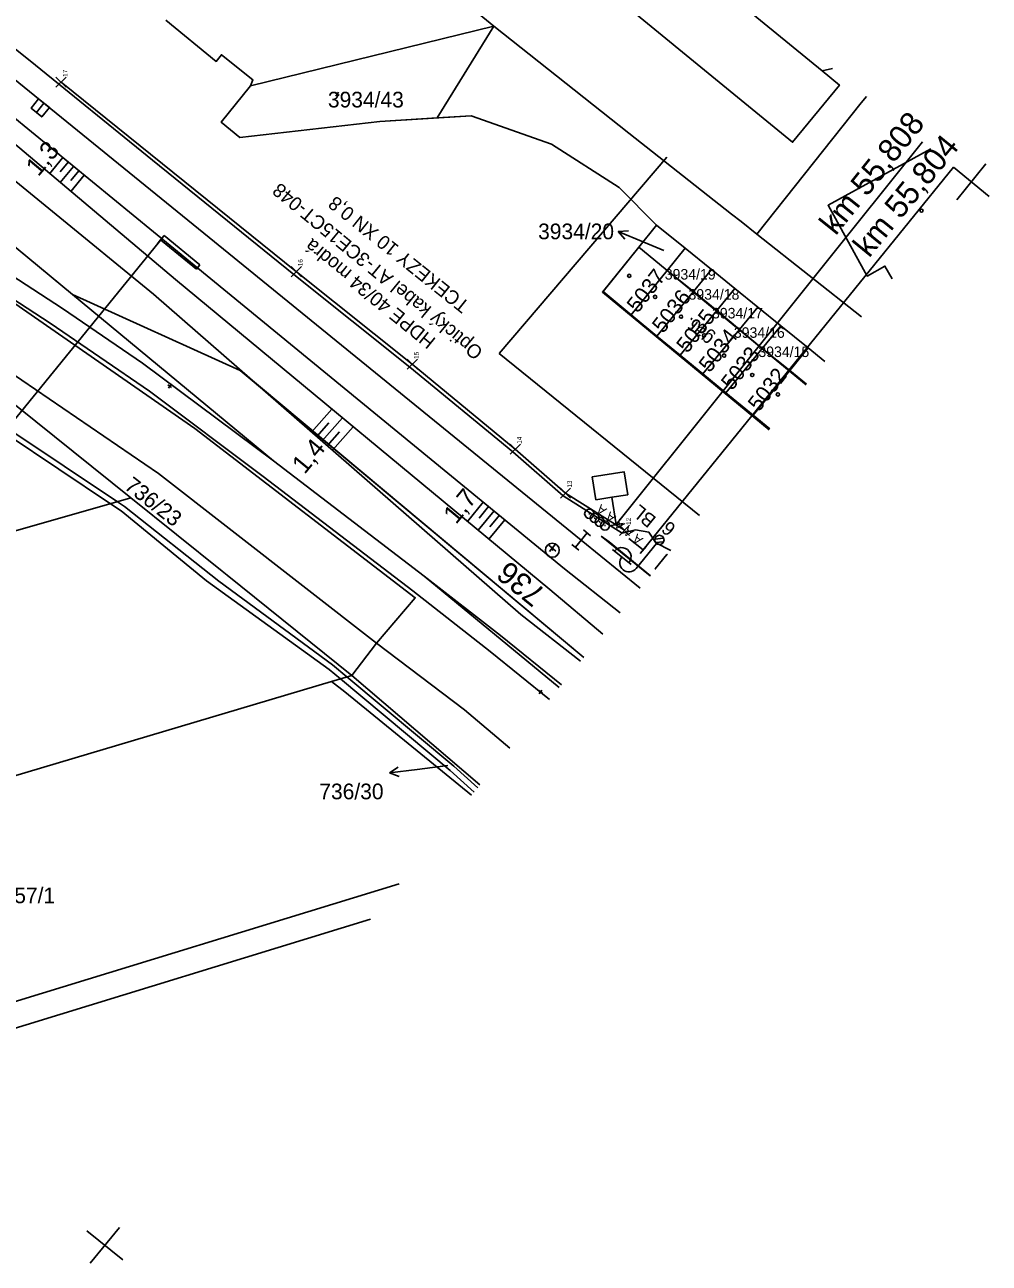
# Model space of a CAD drawing. Extents: x -834676 to -834416, y -1108532 to -1108280.
# Drawn here: x -834520.4 to -834416, y -1108532 to -1108397.9 of the extents above; entities that cross this region are included whole.
import ezdxf

# ---------------------------------------------------------------- set-up
doc = ezdxf.new("R2010")
doc.units = 0
for name, color, linetype in [('Hranice parcel', 7, 'Continuous'), ('Parcelní čísla', 7, 'Continuous'), ('Pop  PČ popisy', 7, 'Continuous'), ('PS 1301 GDIS Nový stav_Prvky_1000', 7, 'Continuous'), ('PS 1301 GDIS Nový stav_Trasa', 7, 'Continuous'), ('PS 1301 LomBod_popis', 7, 'Continuous'), ('PS 1301 LomBod_prvek', 7, 'Continuous'), ('Vnitřní kresba', 7, 'Continuous'), ('Vrstva 1', 7, 'Continuous'), ('Vrstva 14', 7, 'Continuous'), ('Vrstva 17', 7, 'Continuous'), ('Vrstva 23', 7, 'Continuous'), ('Vrstva 25', 7, 'Continuous'), ('Vrstva 27', 7, 'Continuous'), ('Vrstva 3', 7, 'Continuous'), ('Vrstva 32', 7, 'Continuous'), ('Vrstva 33', 7, 'Continuous'), ('Vrstva 48', 7, 'Continuous'), ('Vrstva 49', 7, 'Continuous'), ('Vrstva 53', 7, 'Continuous'), ('Vrstva 6', 7, 'Continuous'), ('Vrstva 60', 7, 'Continuous'), ('Vrstva 63', 7, 'Continuous'), ('Vrstva 7', 7, 'Continuous'), ('Vrstva 9', 7, 'Continuous'), ('Věcná břemena k části', 7, 'Continuous'), ('Značky budov', 7, 'Continuous')]:
    doc.layers.add(name, color=color, linetype=linetype)

msp = doc.modelspace()

# ---------------------------------------------------------------- linework, layer by layer
at = {"layer": 'Hranice parcel'}
for p, q in [((-834495.96, -1108404.56), (-834469.64, -1108398.1)), ((-834469.64, -1108398.1), (-834475.78, -1108408.03)), ((-834495.96, -1108404.56), (-834495.7, -1108403.89)), ((-834542.17, -1108404.85), (-834515.24, -1108427.13)), ((-834441.15, -1108420.61), (-834429.87, -1108406.4)), ((-834453.93, -1108422.01), (-834452.01, -1108419.63)), ((-834452.01, -1108419.63), (-834448.91, -1108422.14)), ((-834441.15, -1108420.61), (-834442.87, -1108419.25)), ((-834542.58, -1108422.11), (-834508.91, -1108449.17)), ((-834450.86, -1108424.54), (-834453.93, -1108422.01)), ((-834448.91, -1108422.14), (-834450.86, -1108424.54)), ((-834448.91, -1108422.14), (-834446.07, -1108424.44)), ((-834450.86, -1108424.54), (-834454.78, -1108429.35)), ((-834448.01, -1108426.81), (-834450.86, -1108424.54)), ((-834446.07, -1108424.44), (-834448.01, -1108426.81)), ((-834446.07, -1108424.44), (-834443.54, -1108426.49)), ((-834448.01, -1108426.81), (-834451.98, -1108431.65)), ((-834445.51, -1108428.88), (-834448.01, -1108426.81)), ((-834443.54, -1108426.49), (-834445.51, -1108428.88)), ((-834443.54, -1108426.49), (-834441.06, -1108428.5)), ((-834515.24, -1108427.13), (-834493.48, -1108445.13)), ((-834451.98, -1108431.65), (-834454.78, -1108429.35)), ((-834445.51, -1108428.88), (-834449.47, -1108433.71)), ((-834443.05, -1108430.92), (-834445.51, -1108428.88)), ((-834441.06, -1108428.5), (-834443.05, -1108430.92)), ((-834441.06, -1108428.5), (-834438.56, -1108430.52)), ((-834443.05, -1108430.92), (-834447, -1108435.74)), ((-834440.59, -1108433), (-834443.05, -1108430.92)), ((-834438.56, -1108430.52), (-834440.59, -1108433)), ((-834438.56, -1108430.52), (-834435.6, -1108432.92)), ((-834449.47, -1108433.71), (-834451.98, -1108431.65)), ((-834447, -1108435.74), (-834449.47, -1108433.71)), ((-834440.59, -1108433), (-834444.51, -1108437.78)), ((-834437.6, -1108435.37), (-834440.59, -1108433)), ((-834435.6, -1108432.92), (-834437.6, -1108435.37)), ((-834435.6, -1108432.92), (-834433.79, -1108434.39)), ((-834444.51, -1108437.78), (-834447, -1108435.74)), ((-834437.6, -1108435.37), (-834441.56, -1108440.19)), ((-834435.8, -1108436.85), (-834437.6, -1108435.37)), ((-834441.56, -1108440.19), (-834444.51, -1108437.78)), ((-834439.74, -1108441.69), (-834441.56, -1108440.19)), ((-834493.48, -1108445.13), (-834477.16, -1108457.63)), ((-834508.91, -1108449.17), (-834551.74, -1108461.32)), ((-834485, -1108468.39), (-834482.32, -1108464.89)), ((-834487.2, -1108469.05), (-834485, -1108468.39)), ((-834471.13, -1108480.23), (-834485, -1108468.39)), ((-834560.03, -1108490.74), (-834487.2, -1108469.05)), ((-834537.95, -1108508.73), (-834479.86, -1108490.95)), ((-834535.36, -1108510.83), (-834482.97, -1108494.76))]:
    msp.add_line(p, q, dxfattribs=at)
for points in [[(-834434.08, -1108402.94), (-834432.22, -1108404.46), (-834437.29, -1108410.65), (-834462.92, -1108389.64), (-834463.74, -1108390.64), (-834501.14, -1108359.98), (-834500.32, -1108358.97), (-834494.92, -1108352.25)], [(-834469.64, -1108398.1), (-834485.11, -1108385.4), (-834501.55, -1108372.58)], [(-834495.7, -1108403.89), (-834499.11, -1108401.19), (-834499.68, -1108401.9), (-834505.13, -1108397.43)], [(-834442.87, -1108419.25), (-834443.89, -1108418.44), (-834455.01, -1108409.66), (-834469.64, -1108398.1)], [(-834432.99, -1108402.69), (-834434.08, -1108402.94)], [(-834475.78, -1108408.03), (-834481.96, -1108408.42), (-834497.12, -1108410.14), (-834499.16, -1108408.48), (-834495.96, -1108404.56)], [(-834429.87, -1108406.4), (-834429.31, -1108405.69)], [(-834452.01, -1108419.63), (-834456.08, -1108415.54), (-834463.39, -1108410.86), (-834472.09, -1108407.8), (-834475.78, -1108408.03)], [(-834482.32, -1108464.89), (-834478.13, -1108459.97), (-834501.98, -1108441.64), (-834521.49, -1108428.13), (-834543.43, -1108413.95), (-834549.21, -1108409.83)], [(-834493.48, -1108445.13), (-834507.66, -1108434.56), (-834516.33, -1108428.66), (-834541.81, -1108412.04), (-834542.9, -1108413.77)], [(-834422.34, -1108411.36), (-834433.45, -1108417.48), (-834429.22, -1108425.14), (-834427.3, -1108424.07), (-834426.51, -1108425.45)], [(-834463.6, -1108470.98), (-834470.02, -1108465.8), (-834478.4, -1108459.23), (-834494.59, -1108446.84), (-834506.89, -1108437.61), (-834517.65, -1108430.23), (-834542.9, -1108413.77)], [(-834429.85, -1108429.55), (-834441.15, -1108420.61)], [(-834542.58, -1108422.11), (-834525.2, -1108433.38), (-834505.92, -1108446.53), (-834482.32, -1108464.89)], [(-834454.78, -1108429.35), (-834457.81, -1108426.82), (-834453.93, -1108422.01)], [(-834459.9, -1108466.45), (-834497.07, -1108435.35), (-834515.24, -1108427.13)], [(-834508.91, -1108449.17), (-834499.04, -1108457.11), (-834498.51, -1108457.53), (-834485, -1108468.39)], [(-834477.16, -1108457.63), (-834468.9, -1108464.07), (-834462.3, -1108469.39)], [(-834462.56, -1108469.7), (-834477.16, -1108457.63)], [(-834482.32, -1108464.89), (-834472.79, -1108472.12), (-834467.9, -1108476.27)], [(-834472.04, -1108481.34), (-834485.74, -1108470.15), (-834487.2, -1108469.05)]]:
    msp.add_lwpolyline(points, dxfattribs=at)
at = {"layer": 'Pop  PČ popisy'}
for p, q in [((-834456.16, -1108420.31), (-834455.05, -1108420.24)), ((-834453.4, -1108421.48), (-834456.16, -1108420.31)), ((-834456.16, -1108420.31), (-834455.44, -1108421.16)), ((-834451.23, -1108422.39), (-834453.4, -1108421.48)), ((-834480.92, -1108478.94), (-834479.99, -1108478.32)), ((-834477.94, -1108478.57), (-834480.92, -1108478.94)), ((-834480.92, -1108478.94), (-834479.86, -1108479.31)), ((-834474.6, -1108478.13), (-834477.94, -1108478.57))]:
    msp.add_line(p, q, dxfattribs=at)
at = {"layer": 'PS 1301 GDIS Nový stav_Prvky_1000'}
for points in [[(-834518.9, -1108405.95), (-834517.74, -1108406.9), (-834518.56, -1108407.91), (-834519.72, -1108406.96)], [(-834517.74, -1108406.9), (-834518.32, -1108406.43), (-834519.14, -1108407.44), (-834518.56, -1108407.91)]]:
    msp.add_lwpolyline(points, close=True, dxfattribs=at)
at = {"layer": 'PS 1301 GDIS Nový stav_Trasa'}
msp.add_lwpolyline([(-834455.48, -1108452.67), (-834461.87, -1108448.64), (-834467.31, -1108443.89), (-834478.46, -1108434.69), (-834491, -1108424.67), (-834516.47, -1108404.15)], dxfattribs=at)
at = {"layer": 'PS 1301 LomBod_prvek'}
for p, q in [((-834517.02, -1108404.7), (-834515.92, -1108403.6)), ((-834515.92, -1108404.7), (-834517.02, -1108403.6)), ((-834516.47, -1108404.15), (-834516.47, -1108404.15)), ((-834491.55, -1108425.22), (-834490.45, -1108424.12)), ((-834490.45, -1108425.22), (-834491.55, -1108424.12)), ((-834491, -1108424.67), (-834491, -1108424.67)), ((-834479.01, -1108435.24), (-834477.91, -1108434.14)), ((-834477.91, -1108435.24), (-834479.01, -1108434.14)), ((-834478.46, -1108434.69), (-834478.46, -1108434.69)), ((-834467.86, -1108444.44), (-834466.76, -1108443.34)), ((-834466.76, -1108444.44), (-834467.86, -1108443.34)), ((-834467.31, -1108443.89), (-834467.31, -1108443.89)), ((-834462.42, -1108449.19), (-834461.32, -1108448.09)), ((-834461.32, -1108449.19), (-834462.42, -1108448.09)), ((-834461.87, -1108448.64), (-834461.87, -1108448.64)), ((-834456.03, -1108453.22), (-834454.93, -1108452.12)), ((-834454.93, -1108453.22), (-834456.03, -1108452.12)), ((-834455.48, -1108452.67), (-834455.48, -1108452.67))]:
    msp.add_line(p, q, dxfattribs=at)
at = {"layer": 'Vnitřní kresba'}
msp.add_line((-834449.27, -1108390.49), (-834434.08, -1108402.94), dxfattribs=at)
at = {"layer": 'Vrstva 1'}
msp.add_lwpolyline([(-834453.78, -1108458.93), (-834460.17, -1108453.73), (-834500.45, -1108420.96), (-834522.77, -1108402.81)], dxfattribs=at)
at = {"layer": 'Vrstva 14'}
for points in [[(-834458.01, -1108453.3), (-834452.71, -1108457.61)], [(-834452.68, -1108457.58), (-834457.15, -1108453.93), (-834458.01, -1108453.3)]]:
    msp.add_lwpolyline(points, dxfattribs=at)
at = {"layer": 'Vrstva 17'}
for points in [[(-834469.05, -1108433.53), (-834450.92, -1108412.28)], [(-834447.36, -1108451.05), (-834469.05, -1108433.53)]]:
    msp.add_lwpolyline(points, dxfattribs=at)
at = {"layer": 'Vrstva 23'}
for points in [[(-834453.92, -1108422), (-834457.88, -1108426.88), (-834439.83, -1108441.8)], [(-834435.84, -1108436.91), (-834453.92, -1108422)]]:
    msp.add_lwpolyline(points, dxfattribs=at)
at = {"layer": 'Vrstva 25'}
for p, q in [((-834451.25, -1108453.52), (-834452.2, -1108453.62)), ((-834454.78, -1108456.37), (-834456.79, -1108454.73)), ((-834452.02, -1108454.1), (-834454.23, -1108456.81)), ((-834451.25, -1108453.9), (-834452.12, -1108453.99))]:
    msp.add_line(p, q, dxfattribs=at)
msp.add_circle((-834451.71, -1108453.71), 0.5, dxfattribs=at)
msp.add_circle((-834451.71, -1108453.71), 0.5, dxfattribs=at)
for centre, start, end in [((-834455.78, -1108455.54), 320.1333, 141.5385), ((-834455.01, -1108456.18), 140.8359, 320.8359)]:
    msp.add_arc(centre, 1, start, end, dxfattribs=at)
at = {"layer": 'Vrstva 27'}
for p, q in [((-834459.35, -1108450.88), (-834459.25, -1108450.88)), ((-834458.77, -1108451.34), (-834458.67, -1108451.34)), ((-834458.22, -1108451.75), (-834458.12, -1108451.75)), ((-834457.65, -1108452.15), (-834457.55, -1108452.15))]:
    msp.add_line(p, q, dxfattribs=at)
for centre in [(-834459.3, -1108450.88), (-834458.72, -1108451.34), (-834458.17, -1108451.75), (-834457.6, -1108452.15)]:
    msp.add_circle(centre, 0.5, dxfattribs=at)
at = {"layer": 'Vrstva 3'}
for p, q in [((-834460.8, -1108454.5), (-834459.54, -1108452.95)), ((-834459.15, -1108453.27), (-834459.93, -1108452.63)), ((-834460.42, -1108454.82), (-834461.19, -1108454.19))]:
    msp.add_line(p, q, dxfattribs=at)
at = {"layer": 'Vrstva 32'}
msp.add_lwpolyline([(-834450.46, -1108454.85), (-834452.1, -1108454.04), (-834452.84, -1108452.88), (-834454.28, -1108452.63), (-834455.74, -1108452.97), (-834462.13, -1108448.94), (-834467.58, -1108444.19), (-834478.72, -1108435), (-834491.26, -1108424.97), (-834506.58, -1108412.6), (-834519.83, -1108401.85), (-834533.51, -1108390.89), (-834533.66, -1108390.74)], dxfattribs=at)
msp.add_lwpolyline([(-834450.46, -1108454.85), (-834452.1, -1108454.04), (-834452.84, -1108452.88), (-834454.28, -1108452.63), (-834455.74, -1108452.97), (-834462.13, -1108448.94), (-834467.58, -1108444.19), (-834478.72, -1108435), (-834491.26, -1108424.97), (-834506.58, -1108412.6), (-834519.83, -1108401.85), (-834533.51, -1108390.89), (-834533.66, -1108390.74)], dxfattribs=at)
msp.add_lwpolyline([(-834450.46, -1108454.85), (-834452.1, -1108454.04), (-834452.84, -1108452.88), (-834454.28, -1108452.63), (-834455.74, -1108452.97), (-834462.13, -1108448.94), (-834467.58, -1108444.19), (-834478.72, -1108435), (-834491.26, -1108424.97), (-834506.58, -1108412.6), (-834519.83, -1108401.85), (-834533.51, -1108390.89), (-834533.66, -1108390.74)], dxfattribs=at)
at = {"layer": 'Vrstva 33'}
msp.add_lwpolyline([(-834452.11, -1108456.87), (-834452.16, -1108456.83), (-834450.9, -1108455.28), (-834450.84, -1108455.32)], dxfattribs=at)
at = {"layer": 'Vrstva 48'}
for p, q in [((-834517.72, -1108414.06), (-834516.29, -1108412.32)), ((-834516.57, -1108413.85), (-834515.71, -1108412.8)), ((-834516.57, -1108415.03), (-834515.13, -1108413.27)), ((-834515.42, -1108414.81), (-834514.55, -1108413.75)), ((-834515.42, -1108416), (-834513.97, -1108414.22)), ((-834487.18, -1108439.54), (-834489.36, -1108442.04)), ((-834487.48, -1108441.03), (-834488.79, -1108442.53)), ((-834486.02, -1108440.5), (-834488.23, -1108443.03)), ((-834484.87, -1108441.46), (-834487.1, -1108444.01)), ((-834486.33, -1108441.99), (-834487.66, -1108443.52)), ((-834472.48, -1108451.71), (-834470.77, -1108449.62)), ((-834471.32, -1108452.67), (-834469.6, -1108450.57)), ((-834471.21, -1108451.35), (-834470.19, -1108450.09)), ((-834470.06, -1108452.3), (-834469.02, -1108451.04)), ((-834470.17, -1108453.62), (-834468.44, -1108451.52))]:
    msp.add_line(p, q, dxfattribs=at)
at = {"layer": 'Vrstva 49'}
for p, q in [((-834486.78, -1108405.31), (-834486.37, -1108405.6)), ((-834486.72, -1108405.66), (-834486.43, -1108405.25)), ((-834504.92, -1108436.93), (-834504.52, -1108437.22)), ((-834504.86, -1108437.28), (-834504.57, -1108436.87)), ((-834464.77, -1108470.02), (-834464.37, -1108470.31)), ((-834464.71, -1108470.37), (-834464.42, -1108469.96))]:
    msp.add_line(p, q, dxfattribs=at)
for points in [[(-834540.18, -1108398.74), (-834538.58, -1108400.19), (-834528.38, -1108409.2), (-834506.48, -1108427.12)], [(-834502.08, -1108423.97), (-834524.11, -1108405.91)], [(-834504.1, -1108425.53), (-834525.82, -1108407.23)], [(-834461.97, -1108456.83), (-834502.08, -1108423.97)], [(-834463.56, -1108459.09), (-834504.1, -1108425.53)], [(-834506.48, -1108427.12), (-834466.71, -1108461.78)], [(-834461.97, -1108456.83), (-834455.97, -1108461.61)], [(-834463.56, -1108459.09), (-834457.85, -1108463.93)], [(-834460.24, -1108466.85), (-834466.71, -1108461.78)]]:
    msp.add_lwpolyline(points, dxfattribs=at)
at = {"layer": 'Vrstva 53'}
for points in [[(-834505.13, -1108397.43), (-834499.68, -1108401.9), (-834499.11, -1108401.19), (-834495.7, -1108403.89), (-834495.96, -1108404.56), (-834499.16, -1108408.48), (-834497.12, -1108410.14), (-834481.96, -1108408.42), (-834472.09, -1108407.8), (-834463.39, -1108410.86), (-834456.08, -1108415.54), (-834452.01, -1108419.63)], [(-834497.07, -1108435.35), (-834515.24, -1108427.13), (-834542.17, -1108404.85)], [(-834452.01, -1108419.63), (-834453.93, -1108422.01), (-834457.81, -1108426.82), (-834454.78, -1108429.35), (-834451.98, -1108431.65), (-834449.47, -1108433.71), (-834447, -1108435.74), (-834444.51, -1108437.78), (-834441.56, -1108440.19), (-834439.74, -1108441.69)], [(-834459.9, -1108466.44), (-834497.07, -1108435.34)]]:
    msp.add_lwpolyline(points, dxfattribs=at)
at = {"layer": 'Vrstva 6'}
for p, q in [((-834453.47, -1108454.8), (-834419.89, -1108413.36)), ((-834455.01, -1108453.55), (-834453.47, -1108454.8)), ((-834453.79, -1108455.19), (-834453.16, -1108454.42))]:
    msp.add_line(p, q, dxfattribs=at)
at = {"layer": 'Vrstva 60'}
for p, q in [((-834416.01, -1108416.52), (-834419.89, -1108413.36)), ((-834416.37, -1108413), (-834419.53, -1108416.88)), ((-834509.8, -1108531.66), (-834513.67, -1108528.5)), ((-834510.16, -1108528.14), (-834513.31, -1108532.02))]:
    msp.add_line(p, q, dxfattribs=at)
at = {"layer": 'Vrstva 63'}
msp.add_line((-834463.26, -1108454.86), (-834463.33, -1108454.79), dxfattribs=at)
msp.add_circle((-834463.3, -1108454.83), 0.756, dxfattribs=at)
at = {"layer": 'Vrstva 7'}
for p, q in [((-834456.39, -1108452.05), (-834423.24, -1108410.63)), ((-834457.14, -1108452.17), (-834455.65, -1108451.94)), ((-834462.91, -1108454.91), (-834463.69, -1108454.28)), ((-834463.61, -1108454.98), (-834462.98, -1108454.21))]:
    msp.add_line(p, q, dxfattribs=at)
msp.add_lwpolyline([(-834456.39, -1108452.05), (-834456.85, -1108449.09), (-834455.13, -1108448.82), (-834455.51, -1108446.35), (-834458.97, -1108446.89), (-834458.58, -1108449.36), (-834456.85, -1108449.09)], dxfattribs=at)
at = {"layer": 'Vrstva 9'}
for p, q in [((-834505.51, -1108420.99), (-834531.76, -1108453.3)), ((-834505.7, -1108421.23), (-834506.08, -1108421.69)), ((-834505.33, -1108420.76), (-834505.7, -1108421.23)), ((-834505.7, -1108421.23), (-834501.82, -1108424.38)), ((-834501.45, -1108423.92), (-834505.33, -1108420.76)), ((-834501.82, -1108424.38), (-834501.45, -1108423.92))]:
    msp.add_line(p, q, dxfattribs=at)
at = {"layer": 'Věcná břemena k části'}
for points in [[(-834556.39, -1108418.64), (-834544.3, -1108427.36), (-834527.95, -1108438.56), (-834511.13, -1108449.8), (-834509.98, -1108450.56), (-834500.72, -1108458.13), (-834487.47, -1108467.73), (-834486.23, -1108468.76), (-834474.36, -1108478.66), (-834471.77, -1108481.01)], [(-834471.38, -1108480.54), (-834473.96, -1108478.22), (-834485.55, -1108468.55), (-834487.11, -1108467.25), (-834499.38, -1108458.16), (-834509.6, -1108450.1), (-834510.36, -1108449.58), (-834527.61, -1108438.06), (-834543.95, -1108426.88), (-834556.01, -1108418.18)]]:
    msp.add_lwpolyline(points, dxfattribs=at)
at = {"layer": 'Značky budov'}
for centre in [(-834423.34, -1108418.06), (-834454.98, -1108425.12), (-834452.18, -1108427.4), (-834449.37, -1108429.54), (-834446.88, -1108431.57), (-834444.71, -1108433.75), (-834441.66, -1108435.85), (-834438.88, -1108437.96)]:
    msp.add_circle(centre, 0.175, dxfattribs=at)

# ---------------------------------------------------------------- texts
at = {"layer": 'Parcelní čísla'}
for s, height, p in [('3934/43', 1.7, (-834487.59, -1108406.89)), ('3934/20', 1.7, (-834464.84, -1108421.16)), ('3934/19', 1.14, (-834451.13, -1108425.52)), ('3934/18', 1.14, (-834448.56, -1108427.7)), ('3934/17', 1.14, (-834446.02, -1108429.73)), ('3934/16', 1.14, (-834443.65, -1108431.83)), ('3934/15', 1.14, (-834441, -1108433.91)), ('736/30', 1.7, (-834488.52, -1108481.79)), ('757/1', 1.7, (-834522.8, -1108493.04))]:
    msp.add_text(s, height=height, dxfattribs=at).set_placement(p)
for s, rotation, p in [('5037', 52, (-834454.05, -1108429.23)), ('5036', 52, (-834451.31, -1108431.44)), ('5035', 52, (-834448.68, -1108433.58)), ('5034', 52, (-834446.26, -1108435.69)), ('5033', 52, (-834443.84, -1108437.62)), ('5032', 52, (-834440.94, -1108439.92)), ('736/23', 322, (-834509.74, -1108448.09))]:
    msp.add_text(s, height=1.7, rotation=rotation, dxfattribs=at).set_placement(p)
at = {"layer": 'PS 1301 LomBod_popis'}
for s, p in [('17', (-834515.78, -1108403.57)), ('16', (-834490.31, -1108424.08)), ('15', (-834477.76, -1108434.11)), ('14', (-834466.62, -1108443.3)), ('13', (-834461.18, -1108448.05)), ('12', (-834454.79, -1108452.08))]:
    msp.add_text(s, height=0.5, rotation=90, dxfattribs=at).set_placement(p)
at = {"layer": 'Vrstva 23'}
msp.add_text('gar.', height=1.5, rotation=140.4238, dxfattribs=at).set_placement((-834445.71, -1108431.71))
at = {"layer": 'Vrstva 25'}
msp.add_text('6', height=1.5, rotation=140.8359, dxfattribs=at).set_placement((-834449.81, -1108452.26))
at = {"layer": 'Vrstva 32'}
for s, rotation, p in [('Optický kabel AT-3CE15CT-048', 140.4778, (-834470.69, -1108433.19)), ('TCEKEZY 10 XN 0,8', 141.3608, (-834472.14, -1108428.08)), ('HDPE 40/34 modrá', 140.8607, (-834475.81, -1108431.98))]:
    msp.add_text(s, height=1.5, rotation=rotation, dxfattribs=at).set_placement(p)
at = {"layer": 'Vrstva 48'}
for s, rotation, p in [('1,3', 49.879, (-834518.93, -1108414.45)), ('1,4', 50.3884, (-834490.11, -1108446.68)), ('1,7', 50.3884, (-834473.72, -1108452.1))]:
    msp.add_text(s, height=2, rotation=rotation, dxfattribs=at).set_placement(p)
at = {"layer": 'Vrstva 6'}
for s, height, rotation, p in [('km 55,804', 2.5, 50.8359, (-834429.01, -1108423.26)), ('  A A A A A ', 1, 140.8359, (-834452.84, -1108454.03)), ('BL', 1.5, 140.8359, (-834451.95, -1108451.34))]:
    msp.add_text(s, height=height, rotation=rotation, dxfattribs=at).set_placement(p)
at = {"layer": 'Vrstva 63'}
msp.add_text('736', height=2.4, rotation=140.871, dxfattribs=at).set_placement((-834463.87, -1108459.24))
at = {"layer": 'Vrstva 7'}
msp.add_text('km 55,808', height=2.5, rotation=51.3289, dxfattribs=at).set_placement((-834432.63, -1108420.85))

doc.saveas('drawing.dxf')
